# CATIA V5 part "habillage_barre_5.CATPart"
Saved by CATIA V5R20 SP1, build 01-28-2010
Part number: habillage_barre_5
Bounding box of the stored display mesh (mm): x 0 to 20, y -1003.257 to -782.811, z 232.468 to 358.7
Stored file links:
  C:\Users\patrice\Desktop\IFMa\Semestre 3\IAO\projet iao\iao\habillage_barre_5.CATPart
  C:\Users\patrice\Desktop\IFMa\Semestre 3\IAO\projet iao\iao\pcabanel.CATProduct
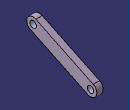
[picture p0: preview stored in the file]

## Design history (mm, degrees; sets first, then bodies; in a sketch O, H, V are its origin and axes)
External parameters (linked from other documents)
  External.AC = 200 mm
Set1
  Plane1: linked copy from another document
  Point1 "G": linked copy from another document
  Point2 "D": linked copy from another document
Body1 (main body)
  Sketch1 on Plane1, origin (0, 0, 0), H (0, 1, 0), V (0, 0, 1)
    construction line L1 (-802.8082, 252.4645) -> (-983.2604, 338.7025)
    point P1 (-802.8082, 252.4645)
    point P2 (-983.2604, 338.7025)
    line L2 (-811.432, 234.4193) -> (-991.8842, 320.6573)
    line L3 (-974.6366, 356.7478) -> (-794.1844, 270.5097)
    arc A1 centre (-983.2604, 338.7025) radius 20 from (-991.8842, 320.6573) to (-974.6366, 356.7478) cw
    arc A2 centre (-802.8082, 252.4645) radius 20 from (-794.1844, 270.5097) to (-811.432, 234.4193) cw
    reference projected point E1 (-983.2604, 338.7025) from Point1
    reference projected point E2 (-802.8082, 252.4645) from Point2
    distance L1 L2 = 20 {= External.AC /10}
    tangency: A1 L2, A2 L2, A1 L3, A2 L3
    coincidence: P2 E1, P1 E2
  Pad1: profile Sketch1, direction (1, 0, 0), length 20 {= External.AC /10}
  Sketch2 on end face of Pad1, origin (20, -245.8151, 84.6756), H (0, 1, 0), V (0, 0, 1)
    point P1 (-737.4453, 254.0269)
    reference projected point E1 (-737.4453, 254.0269) from Point1
    coincidence: E1 P1
  Hole1: placed by Sketch2, at (20, -983.2604, 338.7025) direction (-1, 0, 0), diameter 20 {= External.AC /10}, through (limit type 6)
  Sketch3 on end face of Pad1, origin (20, -200.702, 63.1161), H (0, 1, 0), V (0, 0, 1)
    point P1 (-602.1061, 189.3484)
    reference projected point E1 (-602.1061, 189.3484) from Point2
    coincidence: E1 P1
  Hole2: placed by Sketch3, at (20, -802.8082, 252.4645) direction (-1, 0, 0), diameter 20 {= External.AC /10}, through (limit type 6)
